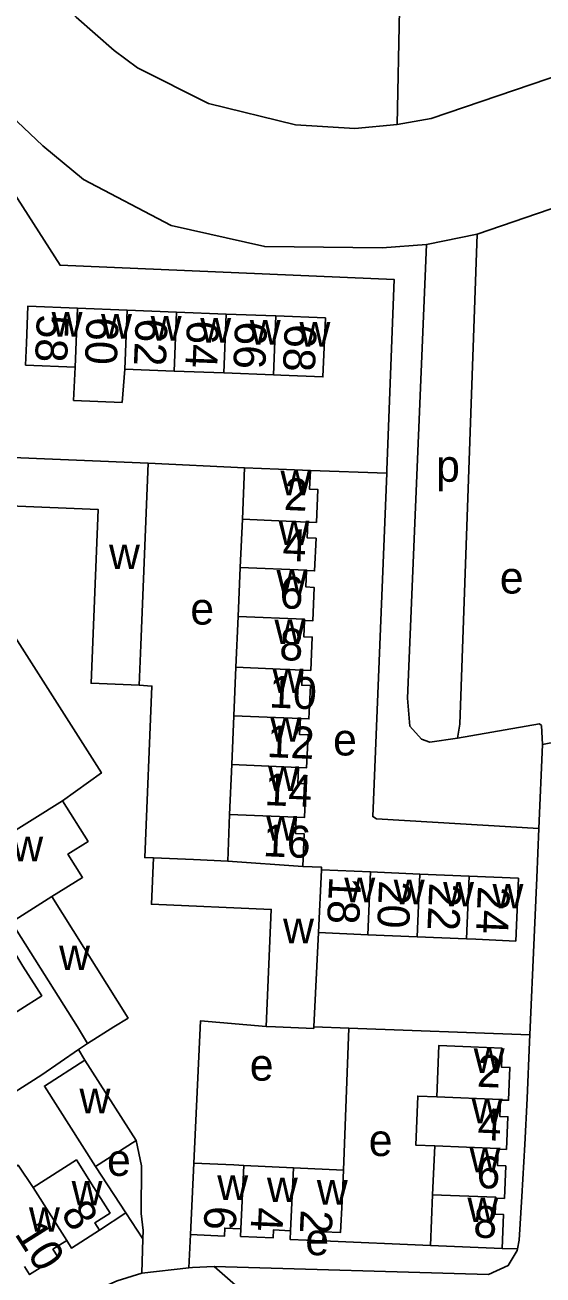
# Model space of a CAD drawing. Extents: x 159675 to 162108, y 386471 to 388472.
# Drawn here: x 160547.3 to 160612.1, y 386719 to 386875.3 of the extents above; entities that cross this region are included whole.
import ezdxf

# ---------------------------------------------------------------- set-up
doc = ezdxf.new("R2010")
doc.units = 0
for name, color, linetype in [('BLT_Basislijn', 7, 'Continuous'), ('BLT_Bebouwing', 7, 'Continuous'), ('BLT_Centroide', 7, 'Continuous'), ('BLT_Huisnummer', 7, 'Continuous'), ('BLT_Huisnummer_ tussenligend', 7, 'Continuous'), ('BLT_Onderverdeling_panden', 7, 'Continuous'), ('BLT_Vlakafsluiter', 7, 'Continuous')]:
    doc.layers.add(name, color=color, linetype=linetype)

msp = doc.modelspace()

# ---------------------------------------------------------------- linework, layer by layer
at = {"layer": 'BLT_Basislijn'}
for p, q in [((160614.46, 386852.78), (160603.9, 386849.14)), ((160603.9, 386849.14), (160597.53, 386847.85)), ((160562.72, 386820.51), (160574.79, 386819.93)), ((160592.57, 386819.24), (160583.02, 386819.58)), ((160612.05, 386785.32), (160674.53, 386797.59)), ((160611.61, 386774.83), (160612.05, 386785.32)), ((160583.46, 386750), (160587.85, 386749.84)), ((160587.16, 386732.1), (160587.85, 386749.84)), ((160587.85, 386749.84), (160610.45, 386748.99)), ((160554.03, 386747.16), (160555.17, 386747.94)), ((160554.83, 386745.83), (160554.03, 386747.16)), ((160559.96, 386726.74), (160556.15, 386732.55)), ((160559.96, 386726.74), (160556.66, 386724.58)), ((160562.09, 386723.49), (160559.96, 386726.74)), ((160561.96, 386719.22), (160562.09, 386723.49)), ((160567.83, 386719.87), (160568.05, 386724.02)), ((160598.05, 386722.65), (160584.59, 386723.24)), ((160608.94, 386722.24), (160607, 386722.28)), ((160561.96, 386719.22), (160567.83, 386719.87))]:
    msp.add_line(p, q, dxfattribs=at)
for points in [[(160551.24, 386878.93), (160553.72, 386876.27), (160558.48, 386872.1), (160561.42, 386869.96), (160570.27, 386865.5), (160581.17, 386862.81), (160588.59, 386862.35), (160593.86, 386862.86)], [(160551.24, 386878.93), (160594.19, 386877.18), (160593.86, 386862.86)], [(160637.62, 386877.04), (160598.11, 386863.6), (160593.86, 386862.86)], [(160597.53, 386847.85), (160592.01, 386847.43), (160577.31, 386847.59), (160565.62, 386850.21), (160554.63, 386855.99), (160549.58, 386860.17), (160546.37, 386863.25), (160543.84, 386862.62), (160539.78, 386868.77)], [(160592.57, 386819.24), (160592.59, 386819.69), (160593.52, 386843.46), (160551.72, 386845.26), (160540.71, 386862.38)], [(160597.53, 386847.85), (160595.15, 386791.13), (160595.48, 386787.63), (160596.93, 386785.98), (160597.98, 386785.62), (160601.42, 386786.13)], [(160603.9, 386849.14), (160601.71, 386787.85), (160601.42, 386786.13)], [(160592.57, 386819.24), (160590.83, 386776.31), (160591.31, 386776.03), (160611.61, 386774.83)], [(160535.37, 386815.57), (160556.9, 386781.77), (160552.02, 386778.29)], [(160563.39, 386771.13), (160562.32, 386771.17), (160563.21, 386792.62), (160561.6, 386792.74)], [(160612.05, 386785.32), (160611.94, 386787.69), (160611.69, 386787.92), (160601.42, 386786.13)], [(160610.45, 386748.99), (160611.02, 386761.2), (160611.33, 386768.64), (160611.61, 386774.83)], [(160568.46, 386732.97), (160569.27, 386750.76), (160577.49, 386750.05)], [(160608.94, 386722.24), (160609.13, 386723.31), (160609.46, 386728.78), (160609.85, 386735.29), (160610.12, 386741.05), (160610.41, 386748.13), (160610.45, 386748.99)], [(160512.17, 386720.25), (160549.42, 386744.02), (160554.03, 386747.16)], [(160561.22, 386735.78), (160561.9, 386732.64), (160561.85, 386726.67), (160562.12, 386724.55), (160562.09, 386723.49)], [(160567.83, 386719.87), (160568.29, 386719.92), (160571.01, 386720.05), (160605.31, 386719.02), (160607.76, 386720.15), (160608.9, 386722.03), (160608.94, 386722.24)], [(160513.15, 386690.17), (160555.58, 386716.8), (160558.86, 386718.25), (160561.96, 386719.22)]]:
    msp.add_lwpolyline(points, dxfattribs=at)
at = {"layer": 'BLT_Bebouwing'}
for p, q in [((160560.1, 386839.65), (160553.9, 386839.9)), ((160566.3, 386839.4), (160560.1, 386839.65)), ((160572.5, 386839.15), (160566.3, 386839.4)), ((160578.7, 386838.91), (160572.5, 386839.15)), ((160559.8, 386832.28), (160566.01, 386832.03)), ((160566.01, 386832.03), (160572.21, 386831.79)), ((160562.72, 386820.51), (160531.58, 386821.77)), ((160574.79, 386819.93), (160574.52, 386813.49)), ((160574.52, 386813.49), (160574.26, 386807.46)), ((160574.26, 386807.46), (160573.99, 386801.32)), ((160573.99, 386801.32), (160573.72, 386794.99)), ((160573.72, 386794.99), (160573.46, 386788.92)), ((160573.46, 386788.92), (160573.2, 386782.81)), ((160573.2, 386782.81), (160572.93, 386776.58)), ((160572.93, 386776.58), (160572.68, 386770.74)), ((160584.42, 386769.65), (160590.53, 386769.39)), ((160590.53, 386769.39), (160596.7, 386769.12)), ((160596.7, 386769.12), (160602.88, 386768.86)), ((160584.02, 386761.8), (160583.46, 386750)), ((160590.19, 386761.53), (160584.02, 386761.8)), ((160596.37, 386761.27), (160590.19, 386761.53)), ((160602.54, 386761.01), (160596.37, 386761.27)), ((160583.45, 386749.8), (160583.46, 386750)), ((160561.22, 386735.78), (160554.83, 386745.83)), ((160556.15, 386732.55), (160561.22, 386735.78)), ((160598.31, 386729.02), (160598.57, 386735.12)), ((160568.46, 386732.97), (160568.05, 386724.02)), ((160574.7, 386732.68), (160580.9, 386732.39)), ((160580.9, 386732.39), (160587.16, 386732.1)), ((160598.05, 386722.65), (160598.31, 386729.02)), ((160607, 386722.28), (160598.05, 386722.65))]:
    msp.add_line(p, q, dxfattribs=at)
for points in [[(160553.9, 386839.9), (160547.69, 386840.14), (160547.51, 386835.51), (160547.4, 386832.77), (160553.6, 386832.52)], [(160578.41, 386831.54), (160579.33, 386831.5), (160584.6, 386831.3), (160584.9, 386838.66), (160578.7, 386838.91)], [(160553.6, 386832.52), (160553.4, 386828.36), (160559.48, 386828.11), (160559.8, 386832.28)], [(160572.21, 386831.79), (160578.41, 386831.54)], [(160562.72, 386820.51), (160561.8, 386797.73), (160561.6, 386792.74)], [(160583.02, 386819.58), (160579.03, 386819.75), (160574.79, 386819.93)], [(160583.02, 386819.58), (160582.93, 386817.25), (160583.96, 386817.2), (160583.78, 386813.1), (160582.72, 386813.14)], [(160561.6, 386792.74), (160555.59, 386792.98), (160556.47, 386814.72), (160535.37, 386815.57)], [(160582.72, 386813.14), (160582.64, 386811.16), (160583.74, 386811.11), (160583.56, 386807.02), (160582.55, 386807.06)], [(160582.55, 386807.06), (160582.46, 386805.02), (160583.49, 386804.97), (160583.31, 386800.78), (160582.29, 386800.83)], [(160582.29, 386800.83), (160582.2, 386798.8), (160583.25, 386798.76), (160583.07, 386794.58), (160582.02, 386794.63)], [(160582.02, 386794.63), (160581.94, 386792.74), (160583.03, 386792.69), (160582.85, 386788.51), (160581.77, 386788.56)], [(160581.77, 386788.56), (160581.68, 386786.55), (160582.73, 386786.51), (160582.55, 386782.41), (160581.53, 386782.46)], [(160581.53, 386782.46), (160581.44, 386780.46), (160582.46, 386780.41), (160582.27, 386776.18), (160581.24, 386776.22)], [(160545.09, 386763.99), (160540.61, 386771.13), (160552.02, 386778.29)], [(160552.02, 386778.29), (160555.22, 386773.19), (160552.7, 386771.61), (160554.53, 386768.7), (160550.69, 386766.29)], [(160581.24, 386776.22), (160581.15, 386774.19), (160582.24, 386774.15), (160582.06, 386770.07)], [(160577.49, 386750.05), (160578.12, 386764.7), (160563.14, 386765.34), (160563.39, 386771.13)], [(160563.39, 386771.13), (160568.39, 386770.92), (160572.68, 386770.74)], [(160582.06, 386770.07), (160584.43, 386769.97), (160584.42, 386769.65)], [(160602.88, 386768.86), (160609.05, 386768.6), (160608.71, 386760.74), (160603.72, 386760.96), (160602.54, 386761.01)], [(160550.69, 386766.29), (160560.22, 386751.1), (160558.46, 386750), (160555.17, 386747.94)], [(160542.37, 386753.45), (160544.14, 386750.56), (160549.42, 386753.89), (160547.08, 386757.6), (160546.17, 386759.05), (160543.63, 386763.07)], [(160555.17, 386747.94), (160553.88, 386750), (160545.64, 386763.12)], [(160577.49, 386750.05), (160578.66, 386750), (160582.49, 386749.85), (160583.45, 386749.8)], [(160598.82, 386741.26), (160599.08, 386747.66), (160603.08, 386747.5), (160607, 386747.34), (160606.91, 386744.97), (160607.98, 386744.93), (160607.81, 386740.82), (160606.8, 386740.86)], [(160554.83, 386745.83), (160549.76, 386742.61), (160556.15, 386732.55)], [(160598.57, 386735.12), (160596.2, 386735.22), (160596.45, 386741.36), (160598.82, 386741.26)], [(160606.8, 386740.86), (160606.71, 386738.8), (160607.72, 386738.76), (160607.55, 386734.68), (160606.51, 386734.72)], [(160606.51, 386734.72), (160606.43, 386732.65), (160607.46, 386732.61), (160607.3, 386728.56), (160606.23, 386728.6)], [(160543.11, 386726.61), (160541.28, 386729.41), (160546.48, 386732.7), (160548.35, 386729.93)], [(160548.35, 386729.93), (160553.77, 386733.36), (160555.96, 386729.91), (160557.98, 386726.71), (160556.07, 386725.51), (160556.66, 386724.58)], [(160574.7, 386732.68), (160573.46, 386732.74), (160568.46, 386732.97)], [(160584.59, 386723.24), (160584.65, 386724.39), (160586.8, 386724.29), (160586.98, 386728.21), (160587.16, 386732.1)], [(160606.23, 386728.6), (160606.15, 386726.58), (160607.18, 386726.54), (160607, 386722.28)], [(160556.66, 386724.58), (160553.14, 386722.35), (160552.55, 386723.28)], [(160568.05, 386724.02), (160572.27, 386723.83), (160572.32, 386724.85), (160574.33, 386724.76)], [(160574.33, 386724.76), (160574.29, 386723.81), (160578.36, 386723.62), (160578.41, 386724.61), (160580.53, 386724.51)], [(160580.53, 386724.51), (160580.48, 386723.43), (160584.59, 386723.24)], [(160552.55, 386723.28), (160550.83, 386722.19), (160551.43, 386721.25), (160547.91, 386719.03), (160547.27, 386720.04)]]:
    msp.add_lwpolyline(points, dxfattribs=at)
at = {"layer": 'BLT_Onderverdeling_panden'}
for p, q in [((160553.6, 386832.52), (160553.9, 386839.9)), ((160559.8, 386832.28), (160560.1, 386839.65)), ((160566.01, 386832.03), (160566.3, 386839.4)), ((160572.21, 386831.79), (160572.5, 386839.15)), ((160578.41, 386831.54), (160578.7, 386838.91)), ((160582.72, 386813.14), (160574.52, 386813.49)), ((160582.02, 386794.63), (160573.72, 386794.99)), ((160581.77, 386788.56), (160573.46, 386788.92)), ((160581.53, 386782.46), (160573.2, 386782.81)), ((160581.24, 386776.22), (160572.93, 386776.58)), ((160572.68, 386770.74), (160582.06, 386770.07)), ((160584.02, 386761.8), (160584.42, 386769.65)), ((160590.19, 386761.53), (160590.53, 386769.39)), ((160596.37, 386761.27), (160596.7, 386769.12)), ((160602.54, 386761.01), (160602.88, 386768.86)), ((160550.69, 386766.29), (160545.64, 386763.12)), ((160574.33, 386724.76), (160574.7, 386732.68)), ((160580.53, 386724.51), (160580.9, 386732.39)), ((160552.55, 386723.28), (160548.35, 386729.93))]:
    msp.add_line(p, q, dxfattribs=at)
for points in [[(160582.55, 386807.06), (160582.55, 386807.14), (160574.26, 386807.46)], [(160582.29, 386800.83), (160582.3, 386800.99), (160573.99, 386801.32)], [(160606.8, 386740.86), (160606.8, 386740.93), (160598.82, 386741.26)], [(160606.51, 386734.72), (160606.51, 386734.8), (160598.57, 386735.12)], [(160606.23, 386728.6), (160606.23, 386728.69), (160598.31, 386729.02)]]:
    msp.add_lwpolyline(points, dxfattribs=at)
at = {"layer": 'BLT_Vlakafsluiter'}
msp.add_line((160571.01, 386720.05), (160586.62, 386706.43), dxfattribs=at)

# ---------------------------------------------------------------- texts
at = {"layer": 'BLT_Centroide'}
for s, p in [('w', (160550.66, 386836.33)), ('w', (160556.84, 386836.09)), ('w', (160563.05, 386835.84)), ('w', (160569.25, 386835.59)), ('w', (160575.45, 386835.34)), ('w', (160581.66, 386835.09)), ('p', (160598.75, 386818.18)), ('w', (160579.28, 386816.5)), ('w', (160579.04, 386810.25)), ('w', (160557.84, 386807.25)), ('w', (160578.78, 386804.09)), ('e', (160606.71, 386804.2)), ('e', (160568.01, 386800.32)), ('w', (160578.53, 386797.88)), ('w', (160578.28, 386791.75)), ('w', (160578.01, 386785.66)), ('e', (160585.86, 386783.95)), ('w', (160577.74, 386779.5)), ('w', (160577.5, 386773.31)), ('w', (160545.74, 386770.72)), ('w', (160587.27, 386765.59)), ('w', (160593.45, 386765.33)), ('w', (160599.62, 386765.06)), ('w', (160605.8, 386764.81)), ('w', (160579.61, 386760.47)), ('w', (160551.6, 386757.11)), ('e', (160575.44, 386743.28)), ('w', (160603.45, 386744.25)), ('w', (160554.15, 386739.19)), ('w', (160603.19, 386737.94)), ('e', (160590.32, 386733.85)), ('e', (160557.59, 386731.37)), ('w', (160602.93, 386731.81)), ('w', (160553.16, 386727.67)), ('w', (160571.38, 386728.36)), ('w', (160577.59, 386728.09)), ('w', (160583.83, 386727.77)), ('w', (160547.83, 386724.38)), ('w', (160602.66, 386725.59)), ('e', (160582.39, 386721.45))]:
    msp.add_text(s, height=4, dxfattribs=at).set_placement(p)
at = {"layer": 'BLT_Huisnummer'}
for s, rotation, p in [('58', 267.7385, (160548.83, 386839.14)), ('62', 267.7385, (160561.18, 386838.66)), ('68', 267.7385, (160579.82, 386837.96)), ('2', 357.5435, (160579.66, 386814.66)), ('6', 357.5435, (160579.12, 386802.37)), ('10', 357.5435, (160577.8, 386789.96)), ('16', 357.5435, (160577.04, 386771.36)), ('18', 267.0921, (160585.41, 386768.89)), ('24', 267.5503, (160603.99, 386767.66)), ('2', 357.6323, (160603.81, 386742.53)), ('8', 302.3176, (160551.73, 386726.69)), ('6', 267.3559, (160569.82, 386727.67)), ('8', 357.6396, (160603.35, 386723.68)), ('2', 267.3559, (160581.83, 386727.18))]:
    msp.add_text(s, height=4, rotation=rotation, dxfattribs=at).set_placement(p)
at = {"layer": 'BLT_Huisnummer_ tussenligend'}
for s, rotation, p in [('60', 267.7317, (160555.05, 386838.84)), ('64', 267.7317, (160567.61, 386838.43)), ('66', 267.7317, (160573.62, 386838.3)), ('4', 357.5435, (160579.49, 386808.32)), ('8', 357.5435, (160579.09, 386795.89)), ('12', 357.5435, (160577.52, 386783.76)), ('14', 357.5435, (160577.23, 386777.75)), ('20', 267.5513, (160591.63, 386768.35)), ('22', 267.5513, (160597.91, 386768.06)), ('4', 357.6371, (160603.88, 386735.88)), ('6', 357.6371, (160603.74, 386729.87)), ('4', 267.3531, (160575.68, 386727.49)), ('10', 302.3176, (160545.95, 386724.13))]:
    msp.add_text(s, height=4, rotation=rotation, dxfattribs=at).set_placement(p)

doc.saveas('drawing.dxf')
